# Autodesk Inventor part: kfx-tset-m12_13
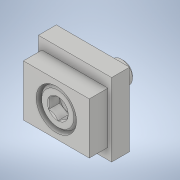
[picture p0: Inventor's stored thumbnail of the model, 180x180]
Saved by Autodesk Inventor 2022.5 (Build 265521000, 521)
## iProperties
Created: 2021-10
Part Number: kfx-tset-m12_13
Material: 一般
Document SubType Name: Modeling
Designer: ImaoCorp
Density: 1 g/cm^3
Appearance: 既定
Author: ImaoCorp
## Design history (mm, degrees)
feature "kfx-tset-m12_13"
node "ソリッド1"
